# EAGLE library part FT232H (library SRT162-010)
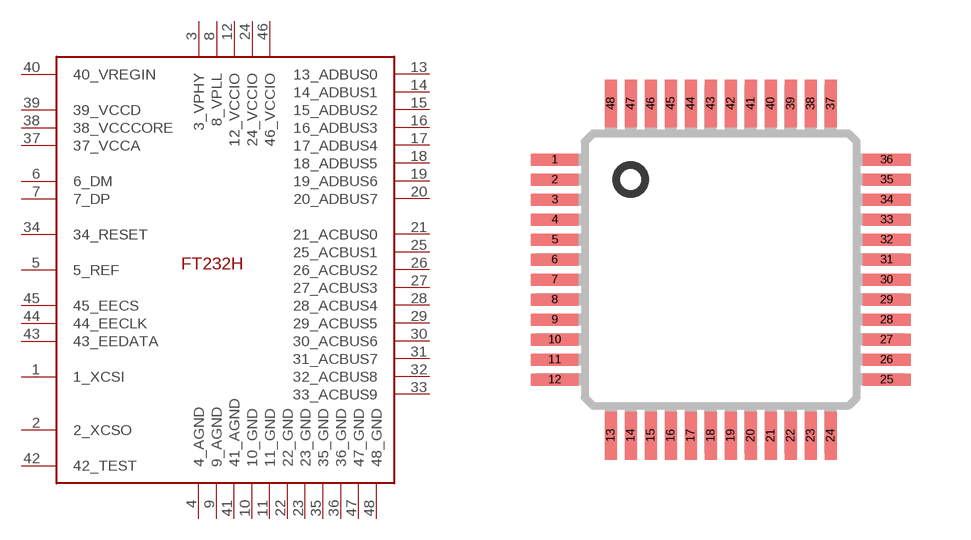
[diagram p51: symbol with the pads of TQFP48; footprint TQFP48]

Designator prefix U

## FT232H  [TQFP48]
1  1_XCSI
2  2_XCSO
3  3_VPHY
4  4_AGND
5  5_REF
6  6_DM
7  7_DP
8  8_VPLL
9  9_AGND
10  10_GND
11  11_GND
12  12_VCCIO
13  13_ADBUS0
14  14_ADBUS1
15  15_ADBUS2
16  16_ADBUS3
17  17_ADBUS4
18  18_ADBUS5
19  19_ADBUS6
20  20_ADBUS7
21  21_ACBUS0
22  22_GND
23  23_GND
24  24_VCCIO
25  25_ACBUS1
26  26_ACBUS2
27  27_ACBUS3
28  28_ACBUS4
29  29_ACBUS5
30  30_ACBUS6
31  31_ACBUS7
32  32_ACBUS8
33  33_ACBUS9
34  34_RESET
35  35_GND
36  36_GND
37  37_VCCA
38  38_VCCCORE
39  39_VCCD
40  40_VREGIN
41  41_AGND
42  42_TEST
43  43_EEDATA
44  44_EECLK
45  45_EECS
46  46_VCCIO
47  47_GND
48  48_GND

## Footprint TQFP48 (pad centres in mm)
smd 1.2 x 0.3: 1 -4.15,2.75; 2 -4.15,2.25; 3 -4.15,1.75; 4 -4.15,1.25; 5 -4.15,0.75; 6 -4.15,0.25; 7 -4.15,-0.25; 8 -4.15,-0.75; 9 -4.15,-1.25; 10 -4.15,-1.75; 11 -4.15,-2.25; 12 -4.15,-2.75; 25 4.15,-2.75; 26 4.15,-2.25; 27 4.15,-1.75; 28 4.15,-1.25; 29 4.15,-0.75; 30 4.15,-0.25; 31 4.15,0.25; 32 4.15,0.75; 33 4.15,1.25; 34 4.15,1.75; 35 4.15,2.25; 36 4.15,2.75
smd 0.3 x 1.2: 13 -2.75,-4.15; 14 -2.25,-4.15; 15 -1.75,-4.15; 16 -1.25,-4.15; 17 -0.75,-4.15; 18 -0.25,-4.15; 19 0.25,-4.15; 20 0.75,-4.15; 21 1.25,-4.15; 22 1.75,-4.15; 23 2.25,-4.15; 24 2.75,-4.15; 37 2.75,4.15; 38 2.25,4.15; 39 1.75,4.15; 40 1.25,4.15; 41 0.75,4.15; 42 0.25,4.15; 43 -0.25,4.15; 44 -0.75,4.15; 45 -1.25,4.15; 46 -1.75,4.15; 47 -2.25,4.15; 48 -2.75,4.15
